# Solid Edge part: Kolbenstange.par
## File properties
Username: ahadarics
Dokumentum tartalom típus: 0
Author: ahadarics
Last saved by: ahadarics
Revision: 79
Sűrűség: 0,000 kg/m^3
Pontosság: 0,990
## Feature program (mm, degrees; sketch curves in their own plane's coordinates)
base feature "unnamed BaseFeature 1"
sketch for "unnamed Protrusion 1" plane through (0, 0, -82.25) normal (0, 0, -1) x-axis (0, 1, 0)
  circle centre (0, 0) radius 16
extrude "unnamed Protrusion 1" add finite 48 along -normal
thread "unnamed Thread 1"
chamfer "Letörés_1" setback 0.8
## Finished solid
Body 1: solid body, 17 faces, 29 edges, 14 vertices.
  Faces by surface: plane 9, cylinder 4, cone 2, torus 2
  Edges by curve: circle 13, line 10, intersection 4, ellipse 2
Bounding box of the edges (mm; curved faces can reach further): 32.000 x 32.000 x 180.000, from (-16, -16, -82.25) to (16, 16, 97.75).
Cylindrical faces by radius (mm): R5 x1, R5.75 x1, R6 x1, R16 x1
Conical faces (half-angle, radius in mm at the cone's reference point): 30 deg R5.875 x1, 45 deg R4.2 x1
Toroidal faces (ring radius, tube radius in mm): R5.25 r0.5 x2
Planar faces by outward normal: +x 1, +z 4, -x 1, -z 1, oblique 2
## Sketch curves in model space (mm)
circle centre (0, 0, -82.25) radius 16
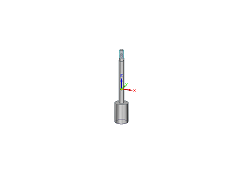
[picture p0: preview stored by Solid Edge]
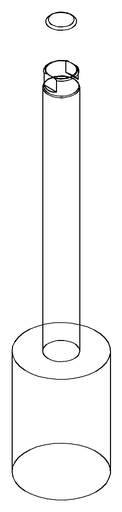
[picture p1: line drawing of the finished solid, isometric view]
